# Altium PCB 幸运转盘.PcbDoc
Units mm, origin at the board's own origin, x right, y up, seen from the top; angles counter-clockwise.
Board outline 152.4 x 101.6 mm, 2 copper layers (Top Layer, Bottom Layer); 22 components, 17 nets, 67 pads, 0 vias.
Unrouted connection lines stored in the file: 44.
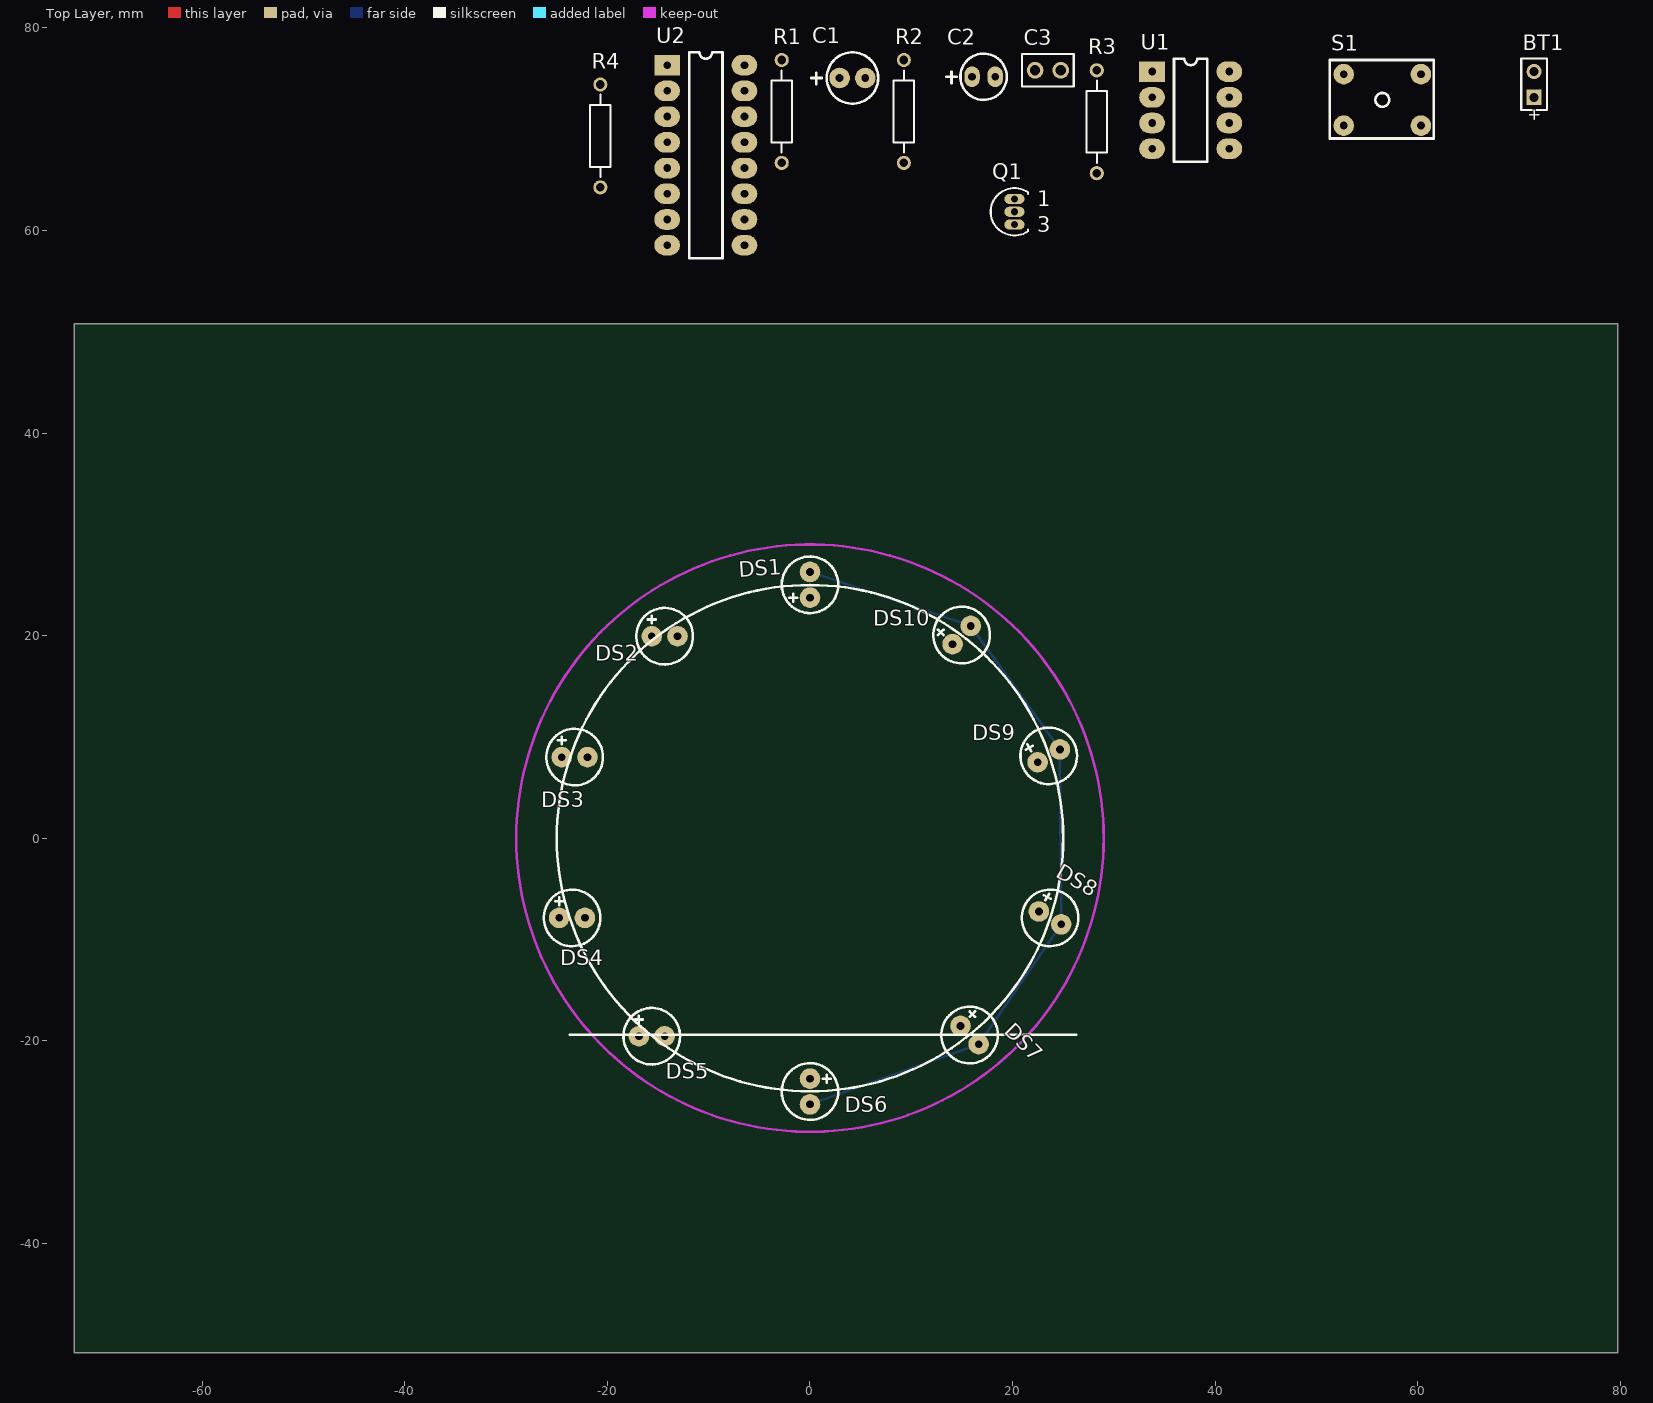
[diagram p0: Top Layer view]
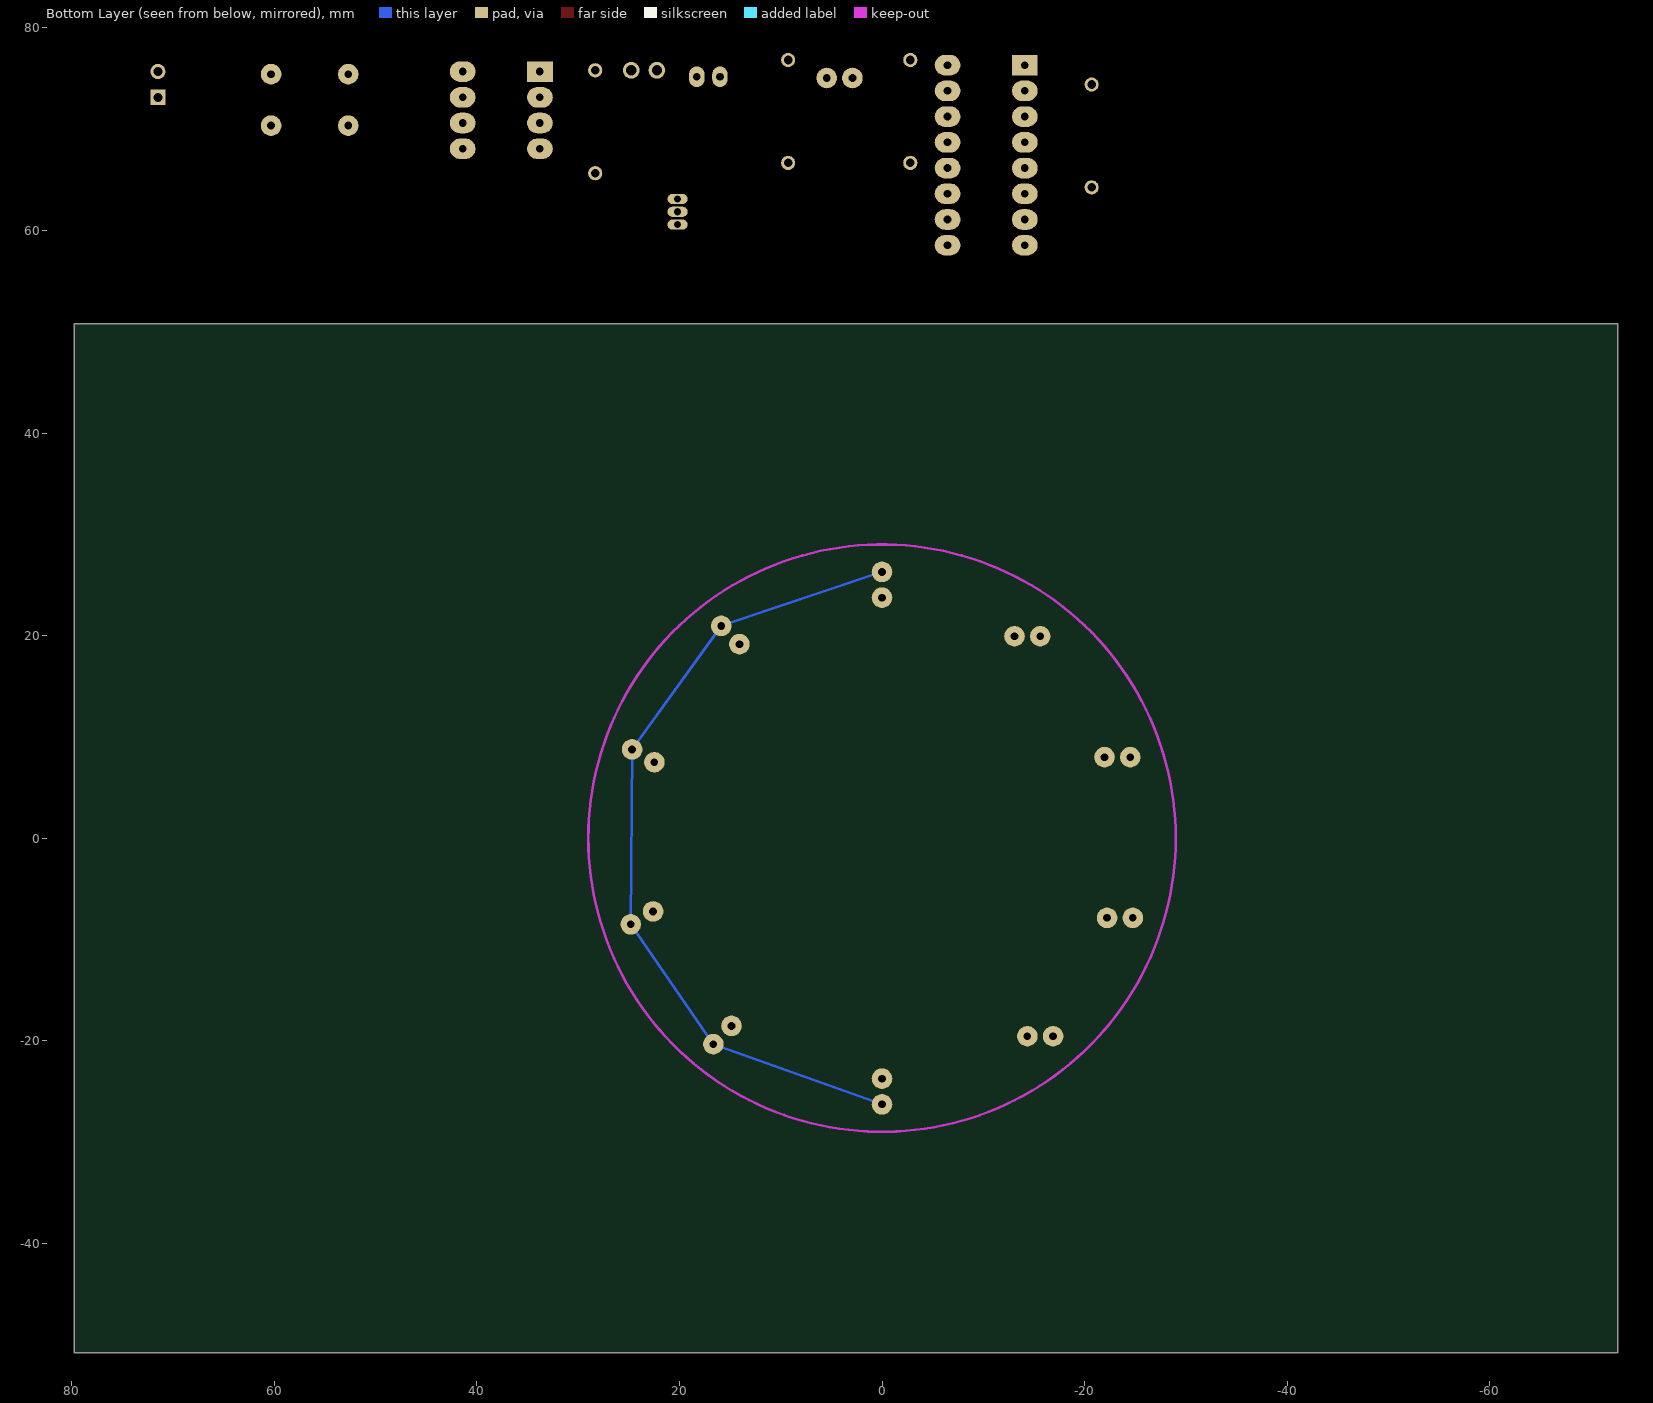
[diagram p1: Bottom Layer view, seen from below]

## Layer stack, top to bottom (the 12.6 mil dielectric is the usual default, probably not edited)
Top Solder: solder mask 0.0102, Solder Resist, Dk 3.5
Top Layer: signal copper 0.0356
Dielectric 1: dielectric 0.32, FR-4, Dk 4.8
Bottom Layer: signal copper 0.0356
Bottom Solder: solder mask 0.0102, Solder Resist, Dk 3.5

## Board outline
-72.644,-50.8 79.756,-50.8 79.756,50.8 -72.644,50.8

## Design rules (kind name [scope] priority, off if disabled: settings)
Clearance [All] p1: gap=0.254
PolygonConnect [All] p1: connectstyle=Relief reliefconductorwidth=0.254 reliefentries=4 polygonreliefangle="90 Angle" airgapwidth=0.254
RoutingVias [All] p1: holewidth=0.711 width=1.27 viastyle="Through Hole" minholewidth=0.711 minwidth=1.27 maxholewidth=0.711 maxwidth=1.27
SolderMaskExpansion [All] p1: expansion=0.102
Width [All] p1: maxlimit=0.254 minlimit=0.254 preferedwidth=0.254
30 further rules are at their usual default settings.

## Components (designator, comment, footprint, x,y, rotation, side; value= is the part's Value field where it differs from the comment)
BT1 "Battery" BAT-2 71.501,74.422 r90 top
C1 "Cap Pol2" 电解电容100uF 2.921,75.057 r0 top
C2 "Cap Pol2" 电解电容47uF 16.002,75.184 r0 top
C3 "Cap" CAPR2.54-5.1X3.2 23.495,75.819 r0 top
DS1 "LED1" 发光二极管 0,23.749 r90 top
DS2 "LED0" 发光二极管 -15.621,19.939 r0 top
DS3 "LED1" 发光二极管 -24.511,8.001 r0 top
DS4 "LED2" 发光二极管 -24.765,-7.874 r0 top
DS5 "LED2" 发光二极管 -16.891,-19.558 r0 top
DS6 "LED0" 发光二极管 0,-23.749 r270 top
DS7 "LED2" 发光二极管 14.859,-18.542 r315 top
DS8 "LED1" 发光二极管 22.606,-7.239 r330 top
DS9 "LED1" 发光二极管 22.479,7.493 r30 top
DS10 "LED1" 发光二极管 14.079,19.159 r45 top
Q1 "2N3904" TO-92 20.193,61.849 r0 top
R1 "Res2" AXIAL-0.4 -2.794,71.755 r90 top
R2 "Res2" AXIAL-0.4 9.271,71.755 r90 top
R3 "Res2" AXIAL-0.4 28.321,70.739 r90 top
R4 "Res2" AXIAL-0.4 -20.701,69.342 r90 top
S1 "SW-PB" 轻触开关 52.705,75.438 r0 top
U1 "NE555N" NE555 33.782,75.692 r0 top
U2 "CD4017BCN" CD4017 -14.097,76.327 r0 top

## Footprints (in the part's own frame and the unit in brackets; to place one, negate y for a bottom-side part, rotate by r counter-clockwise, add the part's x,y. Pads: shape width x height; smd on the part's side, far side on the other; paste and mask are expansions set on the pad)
AXIAL-0.4 [mm] "Axial Device, Thru-Hole; 2 Leads; 0.4 in Pin Spacing"
  round 1.4 hole 0.85: 1(-5.08,0) 2(5.08,0)
  silkscreen extent -4.06,-1.02 4.06,1.02
BAT-2 [mm] "Battery; 2 Leads"
  rect 1.5x1.5 hole 0.9: 1(-1.27,0)
  round 1.5 hole 0.9: 2(1.27,0)
  silkscreen extent -2.54,-1.27 2.54,1.27
CAPR2.54-5.1X3.2 [mm]
  round 1.65 hole 1: 1(-1.27,0) 2(1.27,0)
  silkscreen extent -2.55,-1.6 2.55,1.6
CD4017 [mil]
  rect 100x80 hole 30: 1(0,0)
  oval 100x80 hole 30: 2(0,-100) 3(0,-200) 4(0,-300) 5(0,-400) 6(0,-500) 7(0,-600) 8(0,-700) 9(300,-700) 10(300,-600) 11(300,-500) 12(300,-400) 13(300,-300) 14(300,-200) 15(300,-100) 16(300,0)
  silkscreen extent 85,-750 215,50
NE555 [mil]
  rect 100x80 hole 30: 1(0,0)
  oval 100x80 hole 30: 2(0,-100) 3(0,-200) 4(0,-300) 5(300,-300) 6(300,-200) 7(300,-100) 8(300,0)
  silkscreen extent 85,-350 215,50
TO-92 [mm] "TO, Flat Index; 3 In-Line, Axial Leads; Body Dia. 4.6mm; Leads 0.41 x 0.39 mm (max)"
  oval 2x1 hole 0.7: 1(0,1.27) 2(0,0) 3(0,-1.27)
  silkscreen extent -2.34,-2.34 1.35,2.34
发光二极管 [mil]
  round 80 hole 30: 1(0,0) 2(100,0)
  silkscreen extent -60,-110 160,110
电解电容47uF [mil]
  oval 60x80 hole 30: 1(0,0) 2(90,0)
  silkscreen extent -100,-90 135,90
电解电容100uF [mil]
  round 80 hole 30: 1(0,0) 2(100,0)
  silkscreen extent -110,-100 150,100
轻触开关 [mil]
  round 80 hole 30: 1(0,0) 1(300,0) 2(0,-200) 2(300,-200)
  silkscreen extent -55,-250 350,55

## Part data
BT1: "Multicell Battery"
C1 C2: "Polarized Capacitor (Axial)"
C3: "Capacitor"
DS1 DS3 DS8 DS9 DS10: "Typical RED GaAs LED"
DS2 DS6: "Typical INFRARED GaAs LED"
DS4 DS5 DS7: "Typical RED, GREEN, YELLOW, AMBER GaAs LED"
Q1: "NPN General Purpose Amplifier"
R1 R2 R3 R4: "Resistor"
S1: "Switch"
U1: "General-Purpose Single Bipolar Timer"
U2: "Decade Counter/Divider with 10 Decoded Outputs"

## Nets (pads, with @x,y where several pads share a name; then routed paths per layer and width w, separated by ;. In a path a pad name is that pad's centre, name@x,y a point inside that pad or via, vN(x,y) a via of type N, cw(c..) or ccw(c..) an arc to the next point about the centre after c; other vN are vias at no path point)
GND: BT1.2 C1.2 C2.2 C3.1 DS1.2 DS2.2 DS3.2 DS4.2 DS5.2 DS6.2 DS7.2 DS8.2 DS9.2 DS10.2 R1.1 R2.1 R4.1 R4.2 U1.1 U2.8 U2.13 U2.15 | length 81.1
  Bottom Layer w0.254: DS6.2 DS7.2 DS8.2 DS9.2 DS10.2 DS1.2
NetBT1_1: BT1.1 Q1.3 S1.2 U1.4 U1.8 U2.16
NetC1_1: C1.1 Q1.2 R1.2 S1.1
NetC2_1: C2.1 R2.2 R3.1 U1.2 U1.6 U1.7
NetC3_2: C3.2 U1.5
NetDS1_1: DS1.1 U2.3
NetDS2_1: DS2.1 U2.2
NetDS3_1: DS3.1 U2.4
NetDS4_1: DS4.1 U2.7
NetDS5_1: DS5.1 U2.10
NetDS6_1: DS6.1 U2.1
NetDS7_1: DS7.1 U2.5
NetDS8_1: DS8.1 U2.6
NetDS9_1: DS9.1 U2.9
NetDS10_1: DS10.1 U2.11
NetQ1_1: Q1.1 R3.2
NetU1_3: U1.3 U2.14
pads on no net: U2.12

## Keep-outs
Keep-Out Layer:
  circle w0.254: c0,0 r29

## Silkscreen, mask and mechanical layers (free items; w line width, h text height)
Top Overlay:
  circle w0.254: c0,0 r25
  lines w0.254: -23.73,-19.431 26.27,-19.431
Mechanical 1:
  circle w0.254: c0,0 r30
